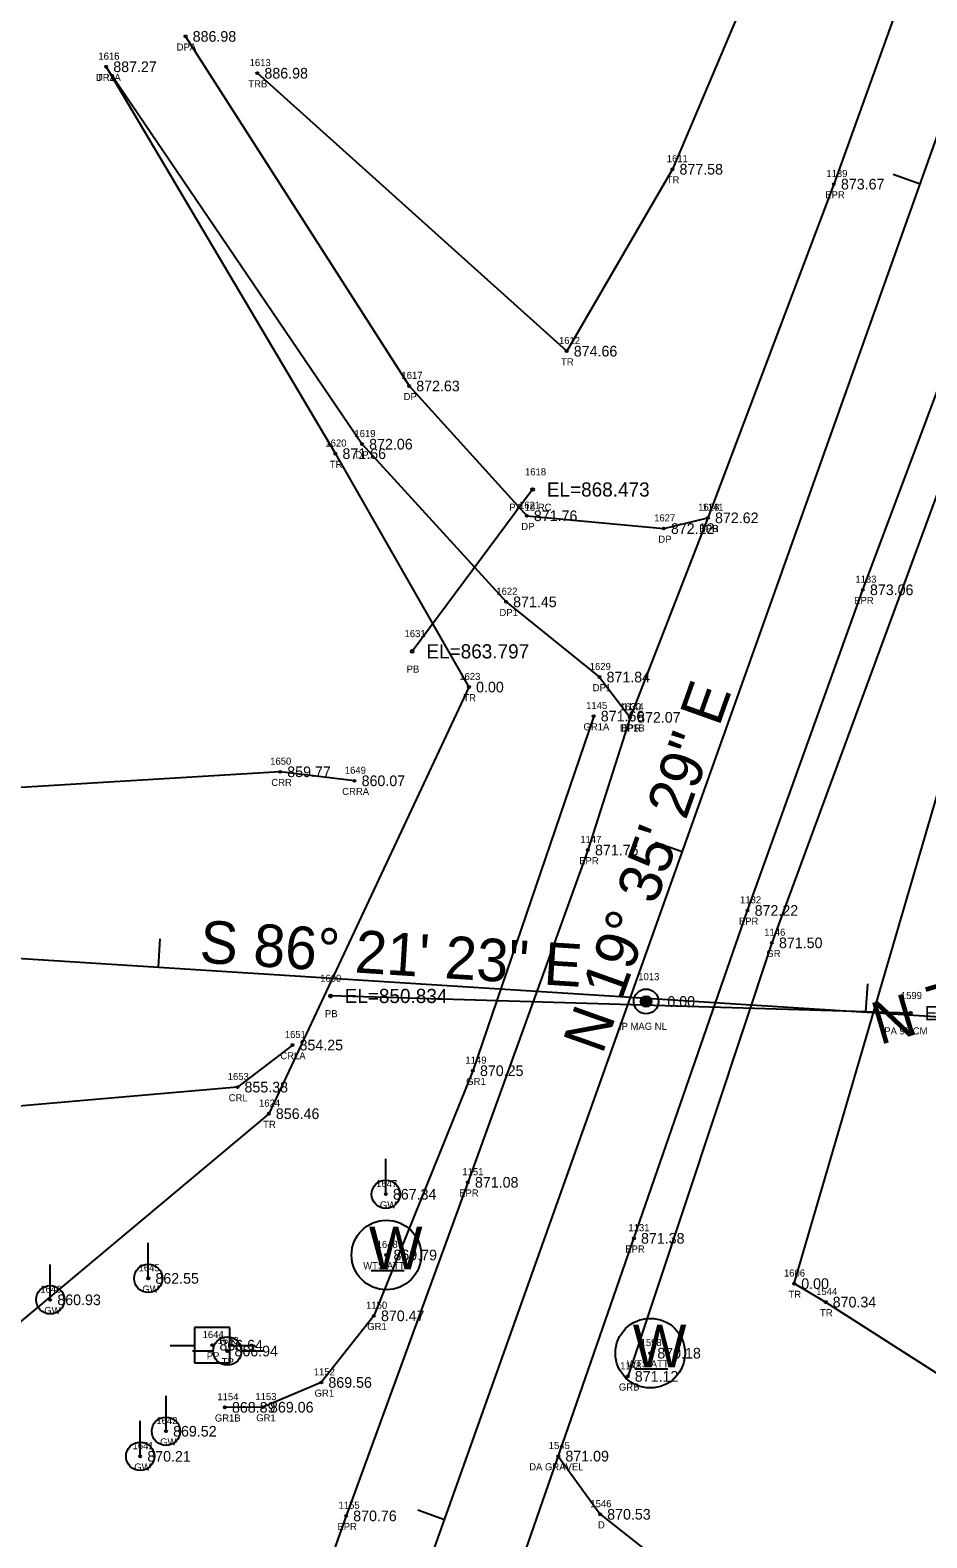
# Model space of a CAD drawing. Extents: x 1448136 to 1453623, y 1125056 to 1128842.
# Drawn here: x 1451149.9 to 1451276.4, y 1127430.4 to 1127643.1 of the extents above; entities that cross this region are included whole.
import ezdxf

# ---------------------------------------------------------------- set-up
doc = ezdxf.new("R2010")
doc.units = 0
for name, color, linetype in [('RD_EX_DR_Pipe', 7, 'Continuous'), ('RD_EX_DR_Pipe_txCode', 7, 'Continuous'), ('RD_EX_Driveway', 7, 'Continuous'), ('RD_EX_Driveway_txCode', 7, 'Continuous'), ('RD_EX_DV_Prop_txCode', 7, 'Continuous'), ('RD_EX_DV_PropPin', 7, 'Continuous'), ('RD_EX_GuardRail', 7, 'Continuous'), ('RD_EX_GuardRail_txCode', 7, 'Continuous'), ('RD_EX_H2O', 7, 'Continuous'), ('RD_EX_H2O_txCode', 7, 'Continuous'), ('RD_EX_Road', 7, 'Continuous'), ('RD_EX_Road_txCode', 7, 'Continuous'), ('RD_EX_TX_Driveway_ELEV', 7, 'Continuous'), ('RD_EX_TX_DV_Prop_ELEV', 7, 'Continuous'), ('RD_EX_TX_GuardRail_ELEV', 7, 'Continuous'), ('RD_EX_TX_H2O_ELEV', 7, 'Continuous'), ('RD_EX_TX_Road_ELEV', 7, 'Continuous'), ('RD_EX_TX_UT_ELEV', 7, 'Continuous'), ('RD_EX_TX_VEG_ELEV', 7, 'Continuous'), ('RD_EX_UT', 7, 'Continuous'), ('RD_EX_UT_txCode', 7, 'Continuous'), ('RD_EX_VEG', 7, 'Continuous'), ('RD_EX_VEG_txCode', 7, 'Continuous'), ('RD_HC_Cl', 7, 'Continuous'), ('RD_HC_Data', 7, 'Continuous'), ('RD_HC_Data_Tic', 7, 'Continuous'), ('RD_HC_Survey_ELEV', 7, 'Continuous'), ('RD_SMD_Locator', 7, 'Continuous'), ('RD_TX_Pipe_ElevEX', 7, 'Continuous')]:
    doc.layers.add(name, color=color, linetype=linetype)

msp = doc.modelspace()

# ---------------------------------------------------------------- linework, layer by layer
at = {"layer": 'RD_EX_DR_Pipe'}
for p, q in [((1451220.81, 1127578.27), (1451203.82, 1127555.44)), ((1451274.09, 1127504.4), (1451192.29, 1127506.83))]:
    msp.add_line(p, q, dxfattribs=at)
at = {"layer": 'RD_EX_Driveway'}
for points in [[(1451171.86, 1127642.18), (1451203.39, 1127592.87), (1451219.98, 1127574.56), (1451239.31, 1127572.76), (1451245.53, 1127574.27)], [(1451160.66, 1127637.9), (1451196.75, 1127584.66), (1451217.06, 1127562.42), (1451230.23, 1127551.81), (1451234.54, 1127546.13)], [(1451224.43, 1127441.92), (1451230.32, 1127433.72), (1451242.65, 1127424), (1451281.31, 1127417.79), (1451309.97, 1127400.35), (1451321.39, 1127371.46), (1451327.64, 1127346.19), (1451348.85, 1127330.18)]]:
    msp.add_lwpolyline(points, dxfattribs=at)
at = {"layer": 'RD_EX_DV_PropPin'}
for p, q in [((1451236.07, 1127505.85), (1451236.07, 1127506.24)), ((1451236.11, 1127505.75), (1451236.11, 1127506.35)), ((1451236.14, 1127505.68), (1451236.14, 1127506.42)), ((1451236.18, 1127505.62), (1451236.18, 1127506.47)), ((1451236.21, 1127505.57), (1451236.21, 1127506.52)), ((1451236.25, 1127505.53), (1451236.25, 1127506.56)), ((1451236.28, 1127505.5), (1451236.28, 1127506.6)), ((1451236.32, 1127505.47), (1451236.32, 1127506.63)), ((1451236.35, 1127505.44), (1451236.35, 1127506.66)), ((1451236.39, 1127505.41), (1451236.39, 1127506.68)), ((1451236.42, 1127505.39), (1451236.42, 1127506.7)), ((1451236.46, 1127505.37), (1451236.46, 1127506.72)), ((1451236.49, 1127505.36), (1451236.49, 1127506.74)), ((1451236.53, 1127505.34), (1451236.53, 1127506.76)), ((1451236.56, 1127505.33), (1451236.56, 1127506.77)), ((1451236.6, 1127505.32), (1451236.6, 1127506.78)), ((1451236.63, 1127505.31), (1451236.63, 1127506.79)), ((1451236.67, 1127505.3), (1451236.67, 1127506.8)), ((1451236.7, 1127505.29), (1451236.7, 1127506.8)), ((1451236.74, 1127505.29), (1451236.74, 1127506.81)), ((1451236.77, 1127505.29), (1451236.77, 1127506.81)), ((1451236.81, 1127505.29), (1451236.81, 1127506.81)), ((1451236.84, 1127505.29), (1451236.84, 1127506.81)), ((1451236.88, 1127505.29), (1451236.88, 1127506.81)), ((1451236.91, 1127505.29), (1451236.91, 1127506.8)), ((1451236.95, 1127505.3), (1451236.95, 1127506.8)), ((1451236.98, 1127505.31), (1451236.98, 1127506.79)), ((1451237.02, 1127505.32), (1451237.02, 1127506.78)), ((1451237.05, 1127505.33), (1451237.05, 1127506.77)), ((1451237.09, 1127505.34), (1451237.09, 1127506.76)), ((1451237.12, 1127505.36), (1451237.12, 1127506.74)), ((1451237.16, 1127505.37), (1451237.16, 1127506.72)), ((1451237.19, 1127505.39), (1451237.19, 1127506.7)), ((1451237.23, 1127505.41), (1451237.23, 1127506.68)), ((1451237.26, 1127505.44), (1451237.26, 1127506.66)), ((1451237.3, 1127505.47), (1451237.3, 1127506.63)), ((1451237.33, 1127505.5), (1451237.33, 1127506.6)), ((1451237.37, 1127505.53), (1451237.37, 1127506.56)), ((1451237.4, 1127505.57), (1451237.4, 1127506.52)), ((1451237.44, 1127505.62), (1451237.44, 1127506.47)), ((1451237.47, 1127505.68), (1451237.47, 1127506.42)), ((1451237.51, 1127505.75), (1451237.51, 1127506.35)), ((1451237.54, 1127505.85), (1451237.54, 1127506.24))]:
    msp.add_line(p, q, dxfattribs=at)
for radius in [1.75, 0.761]:
    msp.add_circle((1451236.81, 1127506.05), radius, dxfattribs=at)
at = {"layer": 'RD_EX_GuardRail'}
for points in [[(1451325.19, 1127708.06), (1451304.64, 1127651.16), (1451284.82, 1127596.54), (1451254.55, 1127514.32), (1451234.22, 1127453.17)], [(1451229.42, 1127546.3), (1451212.38, 1127496.28), (1451198.42, 1127461.71), (1451191, 1127452.31), (1451182.77, 1127448.82), (1451177.4, 1127448.8)]]:
    msp.add_lwpolyline(points, dxfattribs=at)
at = {"layer": 'RD_EX_H2O'}
for points in [[(1451195.69, 1127537.18), (1451185.2, 1127538.45), (1451141.58, 1127535.82), (1451122.17, 1127533.32), (1451063.48, 1127538.6), (1451009.7, 1127550.17), (1450912.81, 1127549.59), (1450858.26, 1127547.2), (1450805.41, 1127571.79), (1450804.49, 1127606.49)], [(1451186.93, 1127499.9), (1451179.17, 1127493.97), (1451140.72, 1127490.62), (1451106.63, 1127492.29), (1451048.45, 1127510.08), (1451003.54, 1127518.51), (1450913.12, 1127519.76), (1450847.92, 1127518.31), (1450803.27, 1127536.05), (1450784.14, 1127535.39), (1450799.36, 1127449.25), (1450771.54, 1127417.41), (1450741.81, 1127369.63), (1450735.37, 1127299.02), (1450712.28, 1127225.28), (1450704.18, 1127161.12), (1450710.83, 1127118.37), (1450722.87, 1127082.49), (1450720.79, 1127059.54), (1450742.04, 1127027.9), (1450729.12, 1127004.03), (1450716.3, 1126986.69), (1450718, 1126972.34), (1450745.7, 1126955.23)]]:
    msp.add_lwpolyline(points, dxfattribs=at)
at = {"layer": 'RD_EX_Road'}
for points in [[(1451297.12, 1127715.11), (1451280.37, 1127668.82), (1451263.29, 1127621.34), (1451245.53, 1127574.27), (1451234.54, 1127546.13), (1451228.6, 1127527.41), (1451211.67, 1127480.54), (1451194.5, 1127433.49), (1451177.84, 1127386.61), (1451172.36, 1127378.15), (1451158.81, 1127368.69), (1451146.18, 1127361.46), (1451101.06, 1127341.11), (1451066.17, 1127324.77), (1451047.03, 1127315.89), (1451024.82, 1127303.57), (1451005, 1127291.25), (1450996.31, 1127285.21), (1450971.96, 1127265.42), (1450935.44, 1127231.03), (1450902.69, 1127193.1), (1450871.02, 1127154.79)], [(1451218.61, 1127425.17), (1451235.09, 1127472.64), (1451251.12, 1127518.89), (1451267.38, 1127564.12), (1451285.5, 1127612.55), (1451301.55, 1127656.07), (1451320.37, 1127708.07)]]:
    msp.add_lwpolyline(points, dxfattribs=at)
at = {"layer": 'RD_EX_UT'}
for p, q in [((1451200.1, 1127478.86), (1451200.1, 1127483.86)), ((1451166.6, 1127466.99), (1451166.6, 1127471.99)), ((1451152.77, 1127463.97), (1451152.77, 1127468.97)), ((1451198.05, 1127468.09), (1451202.68, 1127468.09)), ((1451178.12, 1127460.08), (1451173.12, 1127460.08)), ((1451173.12, 1127460.08), (1451173.12, 1127455.08)), ((1451178.12, 1127455.08), (1451178.12, 1127460.08)), ((1451169.69, 1127457.52), (1451173.16, 1127457.52)), ((1451172.82, 1127456.76), (1451175.75, 1127456.76)), ((1451178.05, 1127457.52), (1451181.69, 1127457.52)), ((1451179.75, 1127456.76), (1451182.82, 1127456.76)), ((1451173.12, 1127455.08), (1451178.12, 1127455.08)), ((1451235.26, 1127454.23), (1451239.89, 1127454.23)), ((1451169.1, 1127445.43), (1451169.1, 1127450.43)), ((1451165.46, 1127441.89), (1451165.46, 1127446.89))]:
    msp.add_line(p, q, dxfattribs=at)
for centre, radius in [((1451200.1, 1127478.86), 2), ((1451200.18, 1127470.29), 4.91), ((1451166.6, 1127466.99), 2), ((1451152.77, 1127463.97), 2), ((1451237.39, 1127456.44), 4.91), ((1451177.75, 1127456.74), 2), ((1451169.1, 1127445.43), 2), ((1451165.46, 1127441.89), 2)]:
    msp.add_circle(centre, radius, dxfattribs=at)
at = {"layer": 'RD_EX_VEG'}
for points in [[(1452001.9, 1127004.02), (1451950.15, 1126969.51), (1451866.38, 1127015.15), (1451796.48, 1127054.28), (1451721.5, 1127099.37), (1451558.29, 1127208.56), (1451484.08, 1127271.15), (1451430.37, 1127335.12), (1451374.3, 1127375.31), (1451350.11, 1127407.35), (1451262.13, 1127463.65), (1451257.69, 1127466.25), (1451295.02, 1127593.73), (1451319.4, 1127654.86), (1451348.07, 1127713.73)], [(1451270.13, 1127693.38), (1451240.52, 1127623.44), (1451225.61, 1127597.78), (1451181.98, 1127636.99)], [(1451160.66, 1127637.9), (1451192.99, 1127583.32), (1451211.83, 1127550.4), (1451183.59, 1127490.22), (1451142.06, 1127455.44), (1451034.7, 1127356.93)]]:
    msp.add_lwpolyline(points, dxfattribs=at)
at = {"layer": 'RD_HC_Cl'}
for p, q in [((1451174.85, 1127338.73), (1451307.37, 1127711.08)), ((1451119.35, 1127514.01), (1451285.28, 1127503.44))]:
    msp.add_line(p, q, dxfattribs=at)
at = {"layer": 'RD_HC_Data_Tic'}
for p, q in [((1451275.44, 1127621.36), (1451271.67, 1127622.7)), ((1451241.91, 1127527.15), (1451238.14, 1127528.49)), ((1451168.02, 1127510.91), (1451168.27, 1127514.9)), ((1451267.82, 1127504.55), (1451268.07, 1127508.54)), ((1451208.38, 1127432.94), (1451204.61, 1127434.28))]:
    msp.add_line(p, q, dxfattribs=at)
at = {"layer": 'RD_SMD_Locator'}
for centre, radius in [((1451171.86, 1127642.18), 0.15), ((1451160.66, 1127637.9), 0.15), ((1451160.66, 1127637.9), 0.15), ((1451181.98, 1127636.99), 0.15), ((1451240.52, 1127623.44), 0.15), ((1451263.29, 1127621.34), 0.15), ((1451225.61, 1127597.78), 0.15), ((1451203.39, 1127592.87), 0.15), ((1451196.75, 1127584.66), 0.15), ((1451192.99, 1127583.32), 0.15), ((1451220.81, 1127578.27), 0.2), ((1451219.98, 1127574.56), 0.15), ((1451245.53, 1127574.27), 0.15), ((1451245.53, 1127574.27), 0.15), ((1451239.31, 1127572.76), 0.15), ((1451217.06, 1127562.42), 0.15), ((1451267.38, 1127564.12), 0.15), ((1451203.82, 1127555.44), 0.2), ((1451230.23, 1127551.81), 0.15), ((1451211.83, 1127550.4), 0.15), ((1451229.42, 1127546.3), 0.15), ((1451234.54, 1127546.13), 0.15), ((1451234.54, 1127546.13), 0.15), ((1451185.2, 1127538.45), 0.15), ((1451195.69, 1127537.18), 0.15), ((1451228.6, 1127527.41), 0.15), ((1451251.12, 1127518.89), 0.15), ((1451254.55, 1127514.32), 0.15), ((1451192.29, 1127506.83), 0.2), ((1451236.81, 1127506.05), 0.15), ((1451274.09, 1127504.4), 0.2), ((1451186.93, 1127499.9), 0.15), ((1451212.38, 1127496.28), 0.15), ((1451179.17, 1127493.97), 0.15), ((1451183.59, 1127490.22), 0.15), ((1451211.67, 1127480.54), 0.15), ((1451200.1, 1127478.86), 0.15), ((1451235.09, 1127472.64), 0.15), ((1451200.18, 1127470.29), 0.15), ((1451166.6, 1127466.99), 0.15), ((1451257.69, 1127466.25), 0.15), ((1451152.77, 1127463.97), 0.15), ((1451262.13, 1127463.65), 0.15), ((1451198.42, 1127461.71), 0.15), ((1451175.63, 1127457.57), 0.15), ((1451177.75, 1127456.74), 0.15), ((1451237.39, 1127456.44), 0.15), ((1451191, 1127452.31), 0.15), ((1451234.22, 1127453.17), 0.15), ((1451177.4, 1127448.8), 0.15), ((1451182.77, 1127448.82), 0.15), ((1451169.1, 1127445.43), 0.15), ((1451165.46, 1127441.89), 0.15), ((1451224.43, 1127441.92), 0.15), ((1451194.5, 1127433.49), 0.15), ((1451230.32, 1127433.72), 0.15)]:
    msp.add_circle(centre, radius, dxfattribs=at)

# ---------------------------------------------------------------- texts
at = {"layer": 'RD_EX_DR_Pipe_txCode'}
for s, p in [('1618', (1451219.73, 1127580.27)), ('PA 18 RC', (1451217.52, 1127575.27)), ('1631', (1451202.74, 1127557.44)), ('PB', (1451203.04, 1127552.44)), ('1600', (1451190.84, 1127508.83)), ('1599', (1451272.74, 1127506.4)), ('PB', (1451191.51, 1127503.83)), ('PA 96 CM', (1451270.4, 1127501.4))]:
    msp.add_text(s, height=1, dxfattribs=at).set_placement(p)
at = {"layer": 'RD_EX_Driveway_txCode'}
for s, p in [('1615', (1451159.57, 1127638.9)), ('DPA', (1451170.6, 1127640.18)), ('DP1A', (1451159.22, 1127635.9)), ('1617', (1451202.3, 1127593.87)), ('DP', (1451202.61, 1127590.87)), ('1619', (1451195.67, 1127585.66)), ('DP1', (1451195.81, 1127582.66)), ('1621', (1451218.89, 1127575.56)), ('1628', (1451244.16, 1127575.27)), ('DP', (1451219.2, 1127572.56)), ('1627', (1451237.94, 1127573.76)), ('DPB', (1451244.28, 1127572.27)), ('DP', (1451238.53, 1127570.76)), ('1622', (1451215.69, 1127563.42)), ('DP1', (1451216.12, 1127560.42)), ('1629', (1451228.86, 1127552.81)), ('DP1', (1451229.28, 1127549.81)), ('1630', (1451233.13, 1127547.13)), ('DP1B', (1451233.12, 1127544.13)), ('1545', (1451223.08, 1127442.92)), ('DA GRAVEL', (1451220.32, 1127439.92)), ('1546', (1451228.95, 1127434.72)), ('D', (1451230.02, 1127431.72))]:
    msp.add_text(s, height=1, dxfattribs=at).set_placement(p)
at = {"layer": 'RD_EX_DV_Prop_txCode'}
for s, p in [('1013', (1451235.7, 1127509.05)), ('IP MAG NL', (1451232.97, 1127502.05))]:
    msp.add_text(s, height=1, dxfattribs=at).set_placement(p)
at = {"layer": 'RD_EX_GuardRail_txCode'}
for s, p in [('1145', (1451228.35, 1127547.3)), ('GR1A', (1451227.98, 1127544.3)), ('1146', (1451253.47, 1127515.32)), ('GR', (1451253.77, 1127512.32)), ('1149', (1451211.32, 1127497.28)), ('GR1', (1451211.44, 1127494.28)), ('1150', (1451197.32, 1127462.71)), ('GR1', (1451197.48, 1127459.71)), ('1152', (1451189.94, 1127453.31)), ('1148', (1451233.15, 1127454.17)), ('GRB', (1451232.97, 1127451.17)), ('1154', (1451176.34, 1127449.8)), ('1153', (1451181.7, 1127449.82)), ('GR1', (1451190.05, 1127450.31)), ('GR1B', (1451175.99, 1127446.8)), ('GR1', (1451181.82, 1127446.82))]:
    msp.add_text(s, height=1, dxfattribs=at).set_placement(p)
at = {"layer": 'RD_EX_H2O_txCode'}
for s, p in [('1650', (1451183.79, 1127539.45)), ('1649', (1451194.32, 1127538.18)), ('CRR', (1451183.95, 1127536.45)), ('CRRA', (1451193.95, 1127535.18)), ('1651', (1451185.85, 1127500.9)), ('CRLA', (1451185.22, 1127497.9)), ('1653', (1451177.8, 1127494.97)), ('CRL', (1451177.94, 1127491.97))]:
    msp.add_text(s, height=1, dxfattribs=at).set_placement(p)
at = {"layer": 'RD_EX_Road_txCode'}
for s, p in [('1139', (1451262.23, 1127622.34)), ('EPR', (1451262.07, 1127619.34)), ('1141', (1451244.75, 1127575.27)), ('EPR', (1451244.3, 1127572.27)), ('1133', (1451266.32, 1127565.12)), ('EPR', (1451266.15, 1127562.12)), ('1144', (1451233.48, 1127547.13)), ('EPR', (1451233.31, 1127544.13)), ('1147', (1451227.53, 1127528.41)), ('EPR', (1451227.37, 1127525.41)), ('1132', (1451250.06, 1127519.89)), ('EPR', (1451249.89, 1127516.89)), ('1151', (1451210.89, 1127481.54)), ('EPR', (1451210.44, 1127478.54)), ('1131', (1451234.31, 1127473.64)), ('EPR', (1451233.86, 1127470.64)), ('1155', (1451193.43, 1127434.49)), ('EPR', (1451193.27, 1127431.49))]:
    msp.add_text(s, height=1, dxfattribs=at).set_placement(p)
at = {"layer": 'RD_EX_TX_Driveway_ELEV'}
for s, p in [('886.98', (1451172.86, 1127641.43)), ('887.27', (1451161.66, 1127637.15)), ('872.63', (1451204.39, 1127592.12)), ('872.06', (1451197.75, 1127583.91)), ('871.76', (1451220.98, 1127573.81)), ('872.12', (1451240.31, 1127572.01)), ('872.62', (1451246.53, 1127573.52)), ('871.45', (1451218.06, 1127561.67)), ('871.84', (1451231.23, 1127551.06)), ('872.07', (1451235.54, 1127545.38)), ('871.09', (1451225.43, 1127441.17)), ('870.53', (1451231.32, 1127432.97))]:
    msp.add_text(s, height=1.5, dxfattribs=at).set_placement(p)
at = {"layer": 'RD_EX_TX_DV_Prop_ELEV'}
msp.add_text('0.00', height=1.5, dxfattribs=at).set_placement((1451239.81, 1127505.3))
at = {"layer": 'RD_EX_TX_GuardRail_ELEV'}
for s, p in [('871.66', (1451230.42, 1127545.55)), ('871.50', (1451255.55, 1127513.57)), ('870.25', (1451213.38, 1127495.53)), ('870.47', (1451199.42, 1127460.96)), ('869.56', (1451192, 1127451.56)), ('871.12', (1451235.22, 1127452.42)), ('868.89', (1451178.4, 1127448.05)), ('869.06', (1451183.77, 1127448.07))]:
    msp.add_text(s, height=1.5, dxfattribs=at).set_placement(p)
at = {"layer": 'RD_EX_TX_H2O_ELEV'}
for s, p in [('859.77', (1451186.2, 1127537.7)), ('860.07', (1451196.69, 1127536.43)), ('854.25', (1451187.93, 1127499.15)), ('855.38', (1451180.17, 1127493.22))]:
    msp.add_text(s, height=1.5, dxfattribs=at).set_placement(p)
at = {"layer": 'RD_EX_TX_Road_ELEV'}
for s, p in [('873.67', (1451264.29, 1127620.59)), ('872.62', (1451246.53, 1127573.52)), ('873.06', (1451268.38, 1127563.37)), ('872.07', (1451235.54, 1127545.38)), ('871.76', (1451229.6, 1127526.66)), ('872.22', (1451252.12, 1127518.14)), ('871.08', (1451212.67, 1127479.79)), ('871.38', (1451236.09, 1127471.89)), ('870.76', (1451195.5, 1127432.74))]:
    msp.add_text(s, height=1.5, dxfattribs=at).set_placement(p)
at = {"layer": 'RD_EX_TX_UT_ELEV'}
for s, p in [('867.34', (1451201.1, 1127478.11)), ('869.79', (1451201.18, 1127469.54)), ('862.55', (1451167.6, 1127466.24)), ('860.93', (1451153.77, 1127463.22)), ('866.94', (1451178.75, 1127455.99)), ('870.18', (1451238.39, 1127455.69)), ('869.52', (1451170.1, 1127444.68)), ('870.21', (1451166.46, 1127441.14))]:
    msp.add_text(s, height=1.5, dxfattribs=at).set_placement(p)
at = {"layer": 'RD_EX_TX_VEG_ELEV'}
for s, p in [('887.27', (1451161.66, 1127637.15)), ('886.98', (1451182.98, 1127636.24)), ('877.58', (1451241.52, 1127622.69)), ('874.66', (1451226.61, 1127597.03)), ('871.66', (1451193.99, 1127582.57)), ('0.00', (1451212.83, 1127549.65)), ('856.46', (1451184.59, 1127489.47)), ('0.00', (1451258.69, 1127465.5)), ('870.34', (1451263.13, 1127462.9))]:
    msp.add_text(s, height=1.5, dxfattribs=at).set_placement(p)
at = {"layer": 'RD_EX_UT'}
for p in [(1451197.71, 1127468.29), (1451234.93, 1127454.44)]:
    msp.add_text('W', height=6, dxfattribs=at).set_placement(p)
at = {"layer": 'RD_EX_UT_txCode'}
for s, p in [('1647', (1451198.73, 1127479.86)), ('GW', (1451199.26, 1127476.86)), ('1648', (1451198.81, 1127471.29)), ('1645', (1451165.23, 1127467.99)), ('WTS ATT', (1451196.91, 1127468.29)), ('1646', (1451151.37, 1127464.97)), ('GW', (1451165.76, 1127464.99)), ('GW', (1451151.93, 1127461.97)), ('1644', (1451174.26, 1127458.57)), ('1643', (1451176.38, 1127457.74)), ('1598', (1451236.04, 1127457.44)), ('PP', (1451174.85, 1127455.57)), ('TP', (1451176.95, 1127454.74)), ('WTS ATT', (1451234.12, 1127454.44)), ('1642', (1451167.73, 1127446.43)), ('1641', (1451164.38, 1127442.89)), ('GW', (1451168.26, 1127443.43)), ('GW', (1451164.62, 1127439.89))]:
    msp.add_text(s, height=1, dxfattribs=at).set_placement(p)
at = {"layer": 'RD_EX_VEG_txCode'}
for s, p in [('1616', (1451159.55, 1127638.9)), ('1613', (1451180.89, 1127637.99)), ('TRA', (1451159.37, 1127635.9)), ('TRB', (1451180.71, 1127634.99)), ('1611', (1451239.72, 1127624.44)), ('TR', (1451239.72, 1127621.44)), ('1612', (1451224.52, 1127598.78)), ('TR', (1451224.81, 1127595.78)), ('1620', (1451191.58, 1127584.32)), ('TR', (1451192.19, 1127581.32)), ('1623', (1451210.46, 1127551.4)), ('TR', (1451211.03, 1127548.4)), ('1624', (1451182.22, 1127491.22)), ('TR', (1451182.8, 1127488.22)), ('1606', (1451256.25, 1127467.25)), ('TR', (1451256.89, 1127464.25)), ('1544', (1451260.79, 1127464.65)), ('TR', (1451261.34, 1127461.65))]:
    msp.add_text(s, height=1, dxfattribs=at).set_placement(p)
at = {"layer": 'RD_HC_Data'}
for s, rotation, p in [('N 19%%d 35\' 29" E', 70.4087, (1451230.64, 1127498.47)), ('N 73%%d 34\' 05" E', 16.432, (1451269.76, 1127499.9)), ('S 86%%d 21\' 23" E', 356.3564, (1451173.73, 1127511.54))]:
    msp.add_text(s, height=6, rotation=rotation, dxfattribs=at).set_placement(p)
at = {"layer": 'RD_HC_Survey_ELEV'}
msp.add_text('866.64', height=1.5, dxfattribs=at).set_placement((1451176.63, 1127456.82))
at = {"layer": 'RD_TX_Pipe_ElevEX'}
for s, p in [('EL=868.473', (1451222.81, 1127577.27)), ('EL=863.797', (1451205.82, 1127554.44)), ('EL=850.834', (1451194.29, 1127505.83)), ('EL=852.598', (1451276.09, 1127503.4))]:
    msp.add_text(s, height=2, dxfattribs=at).set_placement(p)

doc.saveas('drawing.dxf')
